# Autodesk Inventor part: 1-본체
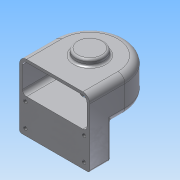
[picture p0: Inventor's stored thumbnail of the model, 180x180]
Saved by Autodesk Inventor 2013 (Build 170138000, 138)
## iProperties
Created: 2015-02
Part Number: 1-본체
Material: 알루미늄 6061
Document SubType Name: Modeling
Designer: Administrator
Density: 2.71 g/cm^3
Mass: 575.526 g
Surface Area: 706.56 cm^2
Volume: 212.371 cm^3
Author: Administrator
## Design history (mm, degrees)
sketch "스케치1"
  geometry: L1 (-50, 0)-(-50, -50); L2 (-50, -50)-(50, -50); L3 (50, -50)-(50, 0); A1 r 50 centre (0, 0) between (50, 0) and (-50, 0); 1 further point
  constraints: 6 end point, 3 tangent, 2 point on circle, 1 centre point, 1 coincident, 1 parallel, 1 perpendicular, 1 vertical
  dimensions: "d0" = 100 diameter of A1
extrude "돌출1" new body sketch "스케치1" distance "d2" = 50; taper "d3" = 0 deg
fillet "모깎기1" dims "d7" = 10
node "작업 평면1"
feature "쉘1" dims "d14" = 4
sketch "스케치4"
  geometry: L1 (-50, -20)-(-34.641, -20); L2 (34.641, -20)-(50, -20); L3 (50, -50)-(50, 0) reference; L4 (-40, -50)-(40, -50) reference; L5 (50, -50)-(40, -50) reference; L6 (-40, -50)-(-50, -50) reference; L7 (-50, 0)-(-50, -50) reference; A1 r 40 centre (0, 0) between (-34.641, -20) and (34.641, -20); 1 further point
  constraints: 4 end point, 2 point on circle, 2 point on line, 1 centre point, 1 coincident, 1 collinear, 1 horizontal
  dimensions: "d8" = 80 diameter of A1; "d10" = 30 distance between parallel lines of L6 L1; "d11" = 30 distance between parallel lines of L5 L2
extrude "돌출2" join sketch "스케치4" stored distance "d12" = 50; taper "d13" = 0 deg
sketch "스케치6"
  geometry: C1 r 25 at (0, 0); A1 r 40 centre (0, 0) between (40, 0) and (-40, 0) reference
  constraints: 1 centre point, 1 coincident
  dimensions: "d15" = 50 diameter of C1
extrude "돌출3" join sketch "스케치6" distance "d17" = 10; taper "d18" = -20 deg
hole "구멍1" diameter "d21" = 20; stored, may be unused: countersink angle "d25" = 90 deg, drill point angle "d27" = 0 deg; dims "d19" = 10, "d20" = 10, "d22" = 6, "d23" = 28, "d24" = 10, "d26" = 14
sketch "스케치7"
  geometry: C1 r 20 at (0, 0); A1 r 40 centre (0, 0) between (40, 0) and (-40, 0) reference
  constraints: 1 centre point, 1 coincident
  dimensions: "d28" = 40 diameter of C1
extrude "돌출4" join sketch "스케치7" distance "d30" = 9; taper "d31" = 0 deg
hole "구멍2" diameter "d34" = 20; stored, may be unused: countersink angle "d38" = 90 deg, drill point angle "d40" = 0 deg; dims "d32" = 10, "d33" = 10, "d35" = 6, "d36" = 28, "d37" = 8, "d39" = 10
fillet "모깎기2" dims "d41" = 3, "d42" = 0.3
fillet "모깎기3" dims "d43" = 3
chamfer "모따기1" distance "d44" = 1; stored, may be unused: second distance "d45" = 2, angle "d46" = 45 deg
sketch "스케치8"
  geometry: C1 r 21.36 at (0, 0) reference; 1 further point
  constraints: 1 horizontal alignment
  dimensions: "d47" = 18 distance of point (18, 0) C1.centre
hole "구멍3" sketch "스케치8" at (18, 0) diameter "d48" = 2.459; stored, may be unused: countersink angle "d52" = 90 deg, drill point angle "d54" = 118 deg; dims "d49" = 6, "d50" = 28, "d51" = 8, "d53" = 9
sketch "스케치9"
  geometry: L1 (-10, -92)-(-10, -10) reference; L2 (-7, -95)-(87, -95) reference; 5 further points
  constraints: 2 horizontal alignment, 2 vertical alignment
  dimensions: "d58" = 9 distance from line of L2 point (-1.75, -86); "d59" = 83.5 distance of point (81.75, -86) point (-1.75, -86); "d60" = 33 distance of point (-1.75, -86) point (-1.75, -53); "d61" = 8.25 distance from line of L1 point (-1.75, -86)
hole "구멍4" sketch "스케치9" at (-1.75, -86), (81.75, -86), (81.75, -53), (-1.75, -53) diameter "d62" = 5.134; stored, may be unused: countersink angle "d66" = 90 deg, drill point angle "d68" = 118 deg; dims "d63" = 10, "d64" = 28, "d65" = 8, "d67" = 13
node "작업 평면2"
sketch "스케치10"
  geometry: L1 (-40, 50)-(40, 50) reference; 2 further points
  constraints: 1 vertical alignment, 1 other
  dimensions: "d69" = 25 distance from line of L1 point (0, 25)
feature "엠보싱1" sketch "스케치10" dims "d0" = 100, "d70" = 0.5, "d71" = 0
node "솔리드1"
pattern_circular "원형 패턴1" dims angle "d56" = 360 deg
other parameters: "d4" = -95
